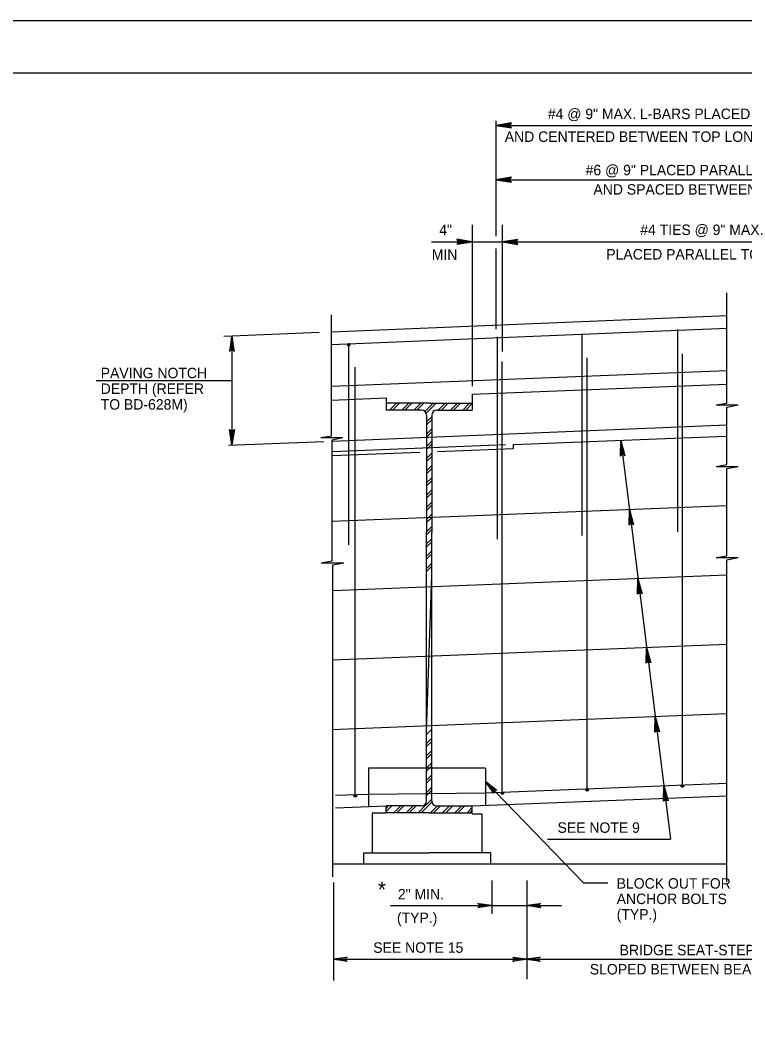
# Model space of a CAD drawing. Extents: x 640009 to 641706, y 298547 to 299735.
# Drawn here: x 641275 to 641482.9, y 299442.5 to 299735.2 of the extents above; entities that cross this region are included whole.
import ezdxf

# ---------------------------------------------------------------- set-up
doc = ezdxf.new("R2010")
doc.units = 0
doc.layers.add('1', color=7, linetype='Continuous')
doc.layers.add('PLT-BNDY', color=7, linetype='Continuous')

msp = doc.modelspace()

# ---------------------------------------------------------------- linework, layer by layer
at = {"layer": '1'}
for p, q in [((640890.47, 299720.17), (641676.47, 299720.17)), ((640890.47, 299720.17), (641676.47, 299720.17)), ((641411.49, 299706.36), (641411.49, 299673.27)), ((641411.49, 299705.06), (641557.24, 299705.06)), ((641411.49, 299689.46), (641557.24, 299689.46)), ((641404.74, 299676.52), (641404.74, 299630.22)), ((641413.37, 299676.52), (641413.37, 299640.22)), ((641393.08, 299671.65), (641571.62, 299671.65)), ((641411.49, 299669.78), (641411.49, 299646.6)), ((641477.87, 299625.37), (641477.87, 299657)), ((641364.37, 299615.97), (641364.37, 299650.72)), ((641364.37, 299645.85), (641477.87, 299650.47)), ((641364.37, 299642.22), (641477.87, 299646.84)), ((641463.62, 299646.47), (641463.62, 299588.47)), ((641333.47, 299644.59), (641360.82, 299645.7)), ((641335.78, 299613.33), (641335.78, 299644.68)), ((641411.87, 299644.35), (641411.87, 299586.35)), ((641436.24, 299645.22), (641436.24, 299587.35)), ((641369.24, 299642.6), (641369.24, 299584.72)), ((641413.37, 299513.42), (641413.37, 299637.35)), ((641437.74, 299514.43), (641437.74, 299638.35)), ((641465.12, 299515.28), (641465.12, 299639.47)), ((641364.37, 299630.22), (641477.87, 299634.72)), ((641371.12, 299512.67), (641371.12, 299635.72)), ((641296.78, 299631.9), (641335.78, 299631.9)), ((641404.74, 299627.9), (641477.87, 299630.84)), ((641364.37, 299626.22), (641379.99, 299626.93)), ((641379.99, 299626.93), (641379.99, 299623.35)), ((641392.37, 299625.35), (641379.99, 299625.35)), ((641392.37, 299625.35), (641379.99, 299625.35)), ((641379.99, 299625.35), (641379.99, 299623.35)), ((641392.37, 299625.35), (641379.99, 299625.35)), ((641379.99, 299625.35), (641379.99, 299624.35)), ((641392.37, 299625.35), (641379.99, 299625.35)), ((641379.99, 299625.35), (641379.99, 299623.35)), ((641392.37, 299625.35), (641404.74, 299625.35)), ((641392.37, 299625.35), (641404.74, 299625.35)), ((641392.37, 299625.35), (641404.74, 299625.35)), ((641392.37, 299625.35), (641404.74, 299625.35)), ((641404.74, 299627.9), (641404.74, 299623.35)), ((641404.74, 299625.35), (641404.74, 299623.35)), ((641404.74, 299625.35), (641404.74, 299624.35)), ((641404.74, 299625.35), (641404.74, 299623.35)), ((641474.74, 299624.87), (641477.87, 299625.37)), ((641390.12, 299623.35), (641379.99, 299623.35)), ((641390.12, 299623.35), (641379.99, 299623.35)), ((641390.12, 299623.35), (641379.99, 299623.35)), ((641394.62, 299623.35), (641404.74, 299623.35)), ((641394.62, 299623.35), (641404.74, 299623.35)), ((641394.62, 299623.35), (641404.74, 299623.35)), ((641474.74, 299624.87), (641481.12, 299624.87)), ((641477.87, 299624.22), (641481.12, 299624.87)), ((641477.87, 299615.9), (641477.87, 299624.22)), ((641477.99, 299624.87), (641477.99, 299624.87)), ((641391.62, 299621.85), (641391.62, 299588.22)), ((641391.62, 299621.85), (641391.62, 299588.22)), ((641391.62, 299621.85), (641391.62, 299588.22)), ((641393.12, 299621.85), (641393.12, 299588.22)), ((641393.12, 299621.85), (641393.12, 299588.22)), ((641393.12, 299621.85), (641393.12, 299588.22)), ((641364.49, 299614.5), (641477.87, 299619.12)), ((641334.74, 299613.29), (641362.1, 299614.4)), ((641361.24, 299615.47), (641364.37, 299615.97)), ((641361.24, 299615.47), (641367.62, 299615.47)), ((641364.49, 299614.85), (641367.62, 299615.47)), ((641364.49, 299615.47), (641364.49, 299615.47)), ((641364.49, 299580.1), (641364.49, 299614.85)), ((641416.62, 299613.47), (641465.12, 299615.39)), ((641447.35, 299614.69), (641461.7, 299500.28)), ((641465.12, 299615.39), (641477.87, 299615.9)), ((641477.87, 299607.73), (641477.87, 299615.9)), ((641364.49, 299611.47), (641414.24, 299613.47)), ((641364.49, 299610.35), (641389.74, 299611.35)), ((641394.74, 299611.47), (641416.62, 299612.35)), ((641416.62, 299612.35), (641416.62, 299613.47)), ((641474.74, 299607.23), (641477.87, 299607.73)), ((641474.74, 299607.23), (641481.12, 299607.23)), ((641477.87, 299606.58), (641481.12, 299607.23)), ((641477.87, 299581.6), (641477.87, 299606.58)), ((641477.99, 299607.23), (641477.99, 299607.23)), ((641364.49, 299591.5), (641477.87, 299595.99)), ((641391.62, 299511.33), (641391.62, 299588.22)), ((641391.62, 299511.33), (641391.62, 299588.22)), ((641391.62, 299511.33), (641391.62, 299588.22)), ((641393.12, 299511.33), (641393.12, 299588.22)), ((641393.12, 299511.33), (641393.12, 299588.22)), ((641393.12, 299511.33), (641393.12, 299588.22)), ((641474.74, 299581.1), (641477.87, 299581.6)), ((641361.37, 299579.6), (641364.49, 299580.1)), ((641361.37, 299579.6), (641367.87, 299579.6)), ((641364.62, 299579.6), (641364.62, 299579.6)), ((641364.74, 299578.97), (641367.87, 299579.6)), ((641364.74, 299489.46), (641364.74, 299578.97)), ((641474.74, 299581.1), (641481.12, 299581.1)), ((641477.87, 299580.45), (641481.12, 299581.1)), ((641477.87, 299488.08), (641477.87, 299580.45)), ((641477.99, 299581.1), (641477.99, 299581.1)), ((641364.74, 299571.6), (641477.87, 299576.09)), ((641364.74, 299551.7), (641477.87, 299556.18)), ((641364.46, 299531.77), (641477.87, 299536.29)), ((641374.92, 299520.65), (641374.92, 299509.6)), ((641408.56, 299520.65), (641374.92, 299520.65)), ((641408.56, 299520.65), (641408.56, 299509.98)), ((641408.56, 299516.78), (641436.71, 299487.74)), ((641408.56, 299513.6), (641477.87, 299516.36)), ((641365.49, 299512.85), (641374.92, 299513.22)), ((641374.92, 299513.22), (641408.56, 299513.6)), ((641404.74, 299509.83), (641477.87, 299512.74)), ((641365.49, 299509.23), (641379.99, 299509.8)), ((641390.12, 299509.83), (641379.99, 299509.83)), ((641379.99, 299507.83), (641379.99, 299509.83)), ((641390.12, 299509.83), (641379.99, 299509.83)), ((641379.99, 299507.83), (641379.99, 299509.83)), ((641390.12, 299509.83), (641379.99, 299509.83)), ((641379.99, 299507.83), (641379.99, 299509.83)), ((641394.62, 299509.83), (641404.74, 299509.83)), ((641394.62, 299509.83), (641404.74, 299509.83)), ((641394.62, 299509.83), (641404.74, 299509.83)), ((641404.74, 299507.83), (641404.74, 299509.83)), ((641404.74, 299507.83), (641404.74, 299509.83)), ((641404.74, 299507.83), (641404.74, 299509.83)), ((641375.99, 299507.83), (641379.99, 299507.83)), ((641375.99, 299507.58), (641375.99, 299496.33)), ((641392.37, 299507.83), (641379.99, 299507.83)), ((641392.37, 299507.83), (641379.99, 299507.83)), ((641392.37, 299507.83), (641379.99, 299507.83)), ((641392.37, 299507.83), (641404.74, 299507.83)), ((641392.37, 299507.83), (641404.74, 299507.83)), ((641392.37, 299507.83), (641404.74, 299507.83)), ((641404.74, 299507.58), (641407.49, 299507.58)), ((641407.49, 299507.58), (641407.49, 299496.33)), ((641426.31, 299500.28), (641461.7, 299500.28)), ((641373.49, 299496.33), (641373.49, 299493.21)), ((641373.49, 299496.33), (641392.37, 299496.33)), ((641409.99, 299496.33), (641392.37, 299496.33)), ((641409.99, 299496.33), (641409.99, 299493.21)), ((641364.74, 299493.21), (641477.87, 299493.21)), ((641364.87, 299487.83), (641364.87, 299459.71)), ((641410.37, 299488.46), (641410.37, 299478.83)), ((641420.37, 299488.46), (641420.37, 299460.08)), ((641436.71, 299487.74), (641443.62, 299487.74)), ((641381.3, 299481.21), (641410.37, 299481.21)), ((641410.37, 299481.21), (641420.37, 299481.21)), ((641420.37, 299481.21), (641430.37, 299481.21)), ((641364.87, 299465.83), (641420.24, 299465.83)), ((641420.24, 299465.83), (641541.87, 299465.83))]:
    msp.add_line(p, q, dxfattribs=at)
for points in [[(641415.78, 299705.58), (641415.6, 299705.27), (641411.54, 299705.04), (641415.78, 299705.58), (641415.99, 299705.77), (641411.54, 299705.04), (641415.6, 299704.85), (641415.76, 299704.54), (641411.54, 299705.04), (641415.99, 299704.32), (641415.76, 299704.54)], [(641415.78, 299689.98), (641415.6, 299689.66), (641411.54, 299689.44), (641415.78, 299689.98), (641415.99, 299690.17), (641411.54, 299689.44), (641415.6, 299689.24), (641415.76, 299688.94), (641411.54, 299689.44), (641415.99, 299688.72), (641415.76, 299688.94)], [(641400.5, 299671.12), (641400.67, 299671.43), (641404.74, 299671.65), (641400.5, 299671.12), (641400.29, 299670.93), (641404.74, 299671.65), (641400.67, 299671.85), (641400.51, 299672.16), (641404.74, 299671.65), (641400.29, 299672.38), (641400.51, 299672.16)], [(641417.65, 299672.18), (641417.48, 299671.86), (641413.41, 299671.64), (641417.65, 299672.18), (641417.87, 299672.36), (641413.41, 299671.64), (641417.48, 299671.44), (641417.64, 299671.14), (641413.41, 299671.64), (641417.87, 299670.91), (641417.64, 299671.14)], [(641336.3, 299640.39), (641335.99, 299640.57), (641335.76, 299644.64), (641336.3, 299640.39), (641336.49, 299640.18), (641335.76, 299644.64), (641335.57, 299640.57), (641335.26, 299640.41), (641335.76, 299644.64), (641335.04, 299640.18), (641335.26, 299640.41)], [(641369.24, 299642.1), (641369.24, 299642.1), (641369.24, 299642.22), (641369.37, 299642.22), (641369.37, 299642.22), (641369.37, 299642.1), (641369.37, 299642.1), (641369.37, 299641.97), (641369.24, 299641.97), (641369.24, 299641.97), (641369.12, 299642.1), (641369.12, 299642.22), (641369.12, 299642.22), (641369.24, 299642.22), (641369.24, 299642.35), (641369.37, 299642.35), (641369.49, 299642.22), (641369.49, 299642.1), (641369.49, 299641.97), (641369.37, 299641.85), (641369.37, 299641.85), (641369.24, 299641.85), (641369.12, 299641.97), (641368.99, 299642.1), (641368.99, 299642.22), (641369.12, 299642.22), (641369.12, 299642.35), (641369.24, 299642.35), (641369.37, 299642.35), (641369.49, 299642.35), (641369.62, 299642.22), (641369.62, 299642.22), (641369.62, 299642.1), (641369.62, 299641.97), (641369.49, 299641.97), (641369.49, 299641.85), (641369.37, 299641.85), (641369.24, 299641.85), (641369.24, 299641.85), (641369.12, 299641.85), (641368.99, 299641.85), (641368.99, 299641.97), (641368.99, 299642.1), (641368.99, 299642.1), (641368.99, 299642.22), (641368.99, 299642.35), (641369.12, 299642.35), (641369.24, 299642.35), (641369.37, 299642.47), (641369.37, 299642.35), (641369.49, 299642.35), (641369.24, 299642.1)], [(641379.99, 299624.97), (641380.37, 299625.35)], [(641380.99, 299623.35), (641382.99, 299625.35)], [(641381.87, 299623.35), (641383.87, 299625.35)], [(641384.49, 299623.35), (641386.49, 299625.35)], [(641385.37, 299623.35), (641387.37, 299625.35)], [(641387.99, 299623.35), (641389.99, 299625.35)], [(641388.87, 299623.35), (641390.87, 299625.35)], [(641391.12, 299622.97), (641393.49, 299625.35)], [(641391.49, 299622.47), (641394.37, 299625.35)], [(641394.99, 299623.35), (641396.99, 299625.35)], [(641395.87, 299623.35), (641397.87, 299625.35)], [(641398.49, 299623.35), (641400.49, 299625.35)], [(641399.37, 299623.35), (641401.37, 299625.35)], [(641401.99, 299623.35), (641403.99, 299625.35)], [(641402.87, 299623.35), (641404.74, 299625.22)], [(641404.62, 299623.35), (641404.74, 299623.47)], [(641391.62, 299619.97), (641393.12, 299621.47)], [(641391.62, 299619.1), (641393.12, 299620.6)], [(641336.3, 299617.62), (641335.99, 299617.44), (641335.76, 299613.38), (641336.3, 299617.62), (641336.49, 299617.83), (641335.76, 299613.38), (641335.57, 299617.44), (641335.26, 299617.6), (641335.76, 299613.38), (641335.04, 299617.83), (641335.26, 299617.6)], [(641391.62, 299616.47), (641393.12, 299617.97)], [(641391.62, 299615.6), (641393.12, 299617.1)], [(641391.62, 299612.97), (641393.12, 299614.47)], [(641391.62, 299612.1), (641393.12, 299613.6)], [(641447.45, 299610.36), (641447.65, 299610.54), (641447.35, 299614.69), (641447.45, 299610.36), (641447.26, 299610.19), (641447.35, 299614.69), (641448.04, 299610.7), (641448.4, 299610.49), (641447.35, 299614.69), (641448.58, 299610.29), (641448.4, 299610.49)], [(641391.62, 299609.47), (641393.12, 299610.97)], [(641391.62, 299608.6), (641393.12, 299610.1)], [(641391.62, 299605.97), (641393.12, 299607.47)], [(641391.62, 299605.1), (641393.12, 299606.6)], [(641391.62, 299602.47), (641393.12, 299603.97)], [(641391.62, 299601.6), (641393.12, 299603.1)], [(641391.62, 299598.97), (641393.12, 299600.47)], [(641391.62, 299598.1), (641393.12, 299599.6)], [(641391.62, 299595.47), (641393.12, 299596.97)], [(641391.62, 299594.6), (641393.12, 299596.1)], [(641391.62, 299591.97), (641393.12, 299593.47)], [(641449.94, 299590.55), (641450.14, 299590.73), (641449.84, 299594.88), (641449.94, 299590.55), (641449.74, 299590.38), (641449.84, 299594.88), (641450.52, 299590.89), (641450.89, 299590.68), (641449.84, 299594.88), (641451.06, 299590.48), (641450.89, 299590.68)], [(641391.62, 299591.1), (641393.12, 299592.6)], [(641391.62, 299588.47), (641393.12, 299589.97)], [(641391.62, 299587.6), (641393.12, 299589.1)], [(641391.62, 299584.97), (641393.12, 299586.47)], [(641391.62, 299584.1), (641393.12, 299585.6)], [(641391.62, 299581.47), (641393.12, 299582.97)], [(641391.62, 299580.6), (641393.12, 299582.1)], [(641391.62, 299577.97), (641393.12, 299579.47)], [(641391.62, 299577.1), (641393.12, 299578.6)], [(641391.62, 299531.21), (641393.12, 299575.97)], [(641452.42, 299570.75), (641452.62, 299570.92), (641452.32, 299575.07), (641452.42, 299570.75), (641452.22, 299570.57), (641452.32, 299575.07), (641453.01, 299571.09), (641453.37, 299570.87), (641452.32, 299575.07), (641453.54, 299570.68), (641453.37, 299570.87)], [(641454.91, 299550.94), (641455.1, 299551.12), (641454.8, 299555.27), (641454.91, 299550.94), (641454.71, 299550.76), (641454.8, 299555.27), (641455.49, 299551.28), (641455.85, 299551.07), (641454.8, 299555.27), (641456.03, 299550.87), (641455.85, 299551.07)], [(641457.39, 299531.14), (641457.59, 299531.32), (641457.29, 299535.47), (641457.39, 299531.14), (641457.19, 299530.97), (641457.29, 299535.47), (641457.97, 299531.48), (641458.34, 299531.27), (641457.29, 299535.47), (641458.51, 299531.07), (641458.34, 299531.27)], [(641391.62, 299530.33), (641393.12, 299531.83)], [(641391.62, 299527.71), (641393.12, 299529.21)], [(641391.62, 299526.83), (641393.12, 299528.33)], [(641391.62, 299524.21), (641393.12, 299525.71)], [(641391.62, 299523.33), (641393.12, 299524.83)], [(641391.62, 299520.71), (641393.12, 299522.21)], [(641391.62, 299519.83), (641393.12, 299521.33)], [(641391.62, 299517.21), (641393.12, 299518.71)], [(641391.62, 299516.33), (641393.12, 299517.83)], [(641391.62, 299513.71), (641393.12, 299515.21)], [(641391.62, 299512.83), (641393.12, 299514.33)], [(641410.91, 299513.84), (641411.01, 299514.1), (641408.56, 299516.78), (641410.91, 299513.84), (641410.91, 299513.49), (641408.56, 299516.78), (641411.27, 299514.37), (641411.54, 299514.45), (641408.56, 299516.78), (641411.8, 299514.36), (641411.54, 299514.45)], [(641437.74, 299514.43), (641437.74, 299514.43), (641437.74, 299514.55), (641437.74, 299514.55), (641437.87, 299514.55), (641437.87, 299514.43), (641437.87, 299514.3), (641437.87, 299514.3), (641437.74, 299514.3), (641437.62, 299514.3), (641437.62, 299514.43), (641437.62, 299514.43), (641437.62, 299514.55), (641437.74, 299514.55), (641437.74, 299514.55), (641437.87, 299514.55), (641437.99, 299514.55), (641437.99, 299514.43), (641437.99, 299514.3), (641437.87, 299514.18), (641437.74, 299514.18), (641437.62, 299514.18), (641437.49, 299514.3), (641437.49, 299514.43), (641437.49, 299514.55), (641437.49, 299514.55), (641437.62, 299514.68), (641437.74, 299514.68), (641437.87, 299514.68), (641437.99, 299514.68), (641437.99, 299514.55), (641437.99, 299514.55), (641437.99, 299514.43), (641437.99, 299514.3), (641437.99, 299514.18), (641437.99, 299514.18), (641437.87, 299514.18), (641437.74, 299514.05), (641437.62, 299514.18), (641437.62, 299514.18), (641437.49, 299514.18), (641437.49, 299514.3), (641437.37, 299514.43), (641437.37, 299514.43), (641437.49, 299514.55), (641437.49, 299514.68), (641437.49, 299514.68), (641437.62, 299514.68), (641437.74, 299514.68), (641437.87, 299514.68), (641437.99, 299514.68), (641437.74, 299514.43)], [(641459.88, 299511.31), (641460.07, 299511.49), (641459.77, 299515.64), (641459.88, 299511.31), (641459.68, 299511.13), (641459.77, 299515.64), (641460.46, 299511.65), (641460.82, 299511.44), (641459.77, 299515.64), (641461, 299511.24), (641460.82, 299511.44)], [(641465.12, 299515.41), (641465.12, 299515.53), (641465.12, 299515.53), (641465.12, 299515.53), (641465.24, 299515.53), (641465.24, 299515.41), (641465.24, 299515.41), (641465.12, 299515.28), (641465.12, 299515.28), (641464.99, 299515.28), (641464.99, 299515.41), (641464.99, 299515.53), (641464.99, 299515.53), (641464.99, 299515.66), (641465.12, 299515.66), (641465.24, 299515.66), (641465.24, 299515.53), (641465.37, 299515.41), (641465.37, 299515.28), (641465.24, 299515.28), (641465.12, 299515.16), (641464.99, 299515.16), (641464.87, 299515.28), (641464.87, 299515.41), (641464.87, 299515.53), (641464.87, 299515.66), (641464.99, 299515.66), (641465.12, 299515.66), (641465.24, 299515.66), (641465.37, 299515.66), (641465.37, 299515.66), (641465.37, 299515.53), (641465.37, 299515.41), (641465.37, 299515.28), (641465.37, 299515.28), (641465.24, 299515.16), (641465.24, 299515.16), (641465.12, 299515.16), (641464.99, 299515.16), (641464.87, 299515.16), (641464.87, 299515.28), (641464.74, 299515.28), (641464.74, 299515.41), (641464.74, 299515.53), (641464.74, 299515.53), (641464.87, 299515.66), (641464.87, 299515.66), (641464.99, 299515.78), (641465.12, 299515.78), (641465.24, 299515.78), (641465.24, 299515.66), (641465.12, 299515.41)], [(641371.12, 299512.67), (641371.12, 299512.79), (641371.12, 299512.79), (641371.24, 299512.79), (641371.24, 299512.79), (641371.37, 299512.79), (641371.24, 299512.67), (641371.24, 299512.54), (641371.12, 299512.54), (641371.12, 299512.54), (641370.99, 299512.67), (641370.99, 299512.79), (641371.12, 299512.79), (641371.12, 299512.92), (641371.24, 299512.92), (641371.24, 299512.92), (641371.37, 299512.79), (641371.37, 299512.67), (641371.37, 299512.54), (641371.37, 299512.54), (641371.24, 299512.42), (641371.12, 299512.54), (641370.99, 299512.54), (641370.87, 299512.67), (641370.87, 299512.79), (641370.99, 299512.92), (641371.12, 299512.92), (641371.12, 299513.04), (641371.24, 299513.04), (641371.37, 299512.92), (641371.49, 299512.92), (641371.49, 299512.79), (641371.49, 299512.67), (641371.49, 299512.54), (641371.49, 299512.54), (641371.37, 299512.42), (641371.24, 299512.42), (641371.24, 299512.42), (641371.12, 299512.42), (641370.99, 299512.42), (641370.87, 299512.54), (641370.87, 299512.54), (641370.87, 299512.67), (641370.87, 299512.79), (641370.87, 299512.79), (641370.87, 299512.92), (641370.99, 299512.92), (641371.12, 299513.04), (641371.24, 299513.04), (641371.24, 299513.04), (641371.37, 299512.92), (641371.12, 299512.67)], [(641391.49, 299510.08), (641393.12, 299511.71)], [(641413.37, 299513.42), (641413.37, 299513.55), (641413.37, 299513.55), (641413.49, 299513.55), (641413.49, 299513.55), (641413.49, 299513.42), (641413.49, 299513.42), (641413.49, 299513.3), (641413.37, 299513.3), (641413.24, 299513.3), (641413.24, 299513.42), (641413.24, 299513.55), (641413.24, 299513.55), (641413.37, 299513.55), (641413.37, 299513.67), (641413.49, 299513.67), (641413.62, 299513.55), (641413.62, 299513.42), (641413.62, 299513.3), (641413.49, 299513.17), (641413.37, 299513.17), (641413.24, 299513.17), (641413.24, 299513.3), (641413.12, 299513.42), (641413.12, 299513.55), (641413.24, 299513.67), (641413.24, 299513.67), (641413.37, 299513.67), (641413.49, 299513.67), (641413.62, 299513.67), (641413.62, 299513.55), (641413.74, 299513.55), (641413.74, 299513.42), (641413.74, 299513.3), (641413.62, 299513.3), (641413.62, 299513.17), (641413.49, 299513.17), (641413.37, 299513.17), (641413.24, 299513.17), (641413.24, 299513.17), (641413.12, 299513.3), (641413.12, 299513.3), (641413.12, 299513.42), (641413.12, 299513.55), (641413.12, 299513.55), (641413.12, 299513.67), (641413.24, 299513.67), (641413.37, 299513.8), (641413.37, 299513.8), (641413.49, 299513.67), (641413.62, 299513.67), (641413.37, 299513.42)], [(641379.99, 299508.21), (641381.62, 299509.83)], [(641379.99, 299509.08), (641380.74, 299509.83)], [(641382.24, 299507.83), (641384.24, 299509.83)], [(641383.12, 299507.83), (641385.12, 299509.83)], [(641385.74, 299507.83), (641387.74, 299509.83)], [(641386.62, 299507.83), (641388.62, 299509.83)], [(641389.24, 299507.83), (641391.37, 299510.08)], [(641390.12, 299507.83), (641393.24, 299510.96)], [(641392.74, 299507.83), (641394.74, 299509.83)], [(641393.62, 299507.83), (641395.62, 299509.83)], [(641396.24, 299507.83), (641398.24, 299509.83)], [(641397.12, 299507.83), (641399.12, 299509.83)], [(641399.74, 299507.83), (641401.74, 299509.83)], [(641400.62, 299507.83), (641402.62, 299509.83)], [(641403.24, 299507.83), (641404.74, 299509.33)], [(641404.12, 299507.83), (641404.74, 299508.46)], [(641406.62, 299481.71), (641406.74, 299481.46), (641410.37, 299481.21), (641406.62, 299481.71), (641406.37, 299481.83), (641410.37, 299481.21), (641406.74, 299481.08), (641406.62, 299480.83), (641410.37, 299481.21), (641406.37, 299480.58), (641406.62, 299480.83)], [(641424.12, 299480.83), (641423.99, 299481.08), (641420.37, 299481.21), (641424.12, 299480.83), (641424.37, 299480.58), (641420.37, 299481.21), (641423.99, 299481.46), (641424.12, 299481.71), (641420.37, 299481.21), (641424.37, 299481.83), (641424.12, 299481.71)], [(641368.62, 299465.33), (641368.49, 299465.58), (641364.87, 299465.83), (641368.62, 299465.33), (641368.87, 299465.21), (641364.87, 299465.83), (641368.49, 299465.96), (641368.62, 299466.33), (641364.87, 299465.83), (641368.87, 299466.46), (641368.62, 299466.33)], [(641416.49, 299466.33), (641416.62, 299466.08), (641420.24, 299465.83), (641416.49, 299466.33), (641416.37, 299466.46), (641420.24, 299465.83), (641416.62, 299465.71), (641416.49, 299465.33), (641420.24, 299465.83), (641416.37, 299465.21), (641416.49, 299465.33)], [(641423.99, 299465.33), (641423.87, 299465.58), (641420.24, 299465.83), (641423.99, 299465.33), (641424.24, 299465.21), (641420.24, 299465.83), (641423.87, 299465.96), (641423.99, 299466.33), (641420.24, 299465.83), (641424.24, 299466.46), (641423.99, 299466.33)]]:
    msp.add_lwpolyline(points, dxfattribs=at)
for centre, start, end in [((641390.16, 299621.87), 0, 90), ((641390.16, 299621.87), 0, 90), ((641390.16, 299621.87), 0, 90), ((641394.62, 299621.87), 90, 180), ((641394.62, 299621.87), 90, 180), ((641394.62, 299621.87), 90, 180), ((641390.16, 299511.29), 270, 0), ((641390.16, 299511.29), 270, 0), ((641390.16, 299511.29), 270, 0), ((641394.62, 299511.29), 180, 270), ((641394.62, 299511.29), 180, 270), ((641394.62, 299511.29), 180, 270)]:
    msp.add_arc(centre, 1.49, start, end, dxfattribs=at)
at = {"layer": 'PLT-BNDY'}
msp.add_lwpolyline([(640850.47, 299735.17), (641691.47, 299735.17), (641691.47, 299141.17), (640850.47, 299141.17)], close=True, dxfattribs=at)

# ---------------------------------------------------------------- texts
at = {"layer": '1'}
for s, height, p in [('#4 @ 9" MAX. L-BARS PLACED PARALLEL TO', 3, (641426.44, 299706.86)), ('AND CENTERED BETWEEN TOP LONGITUDINAL SLAB BARS', 3, (641414.08, 299700.32)), ('#6 @ 9" PLACED PARALLEL TO BEAMS', 3, (641437.29, 299690.73)), ('AND SPACED BETWEEN BEAM FLANGES', 3, (641439.53, 299685.19)), ('4"', 3, (641395.26, 299673.54)), ('#4 TIES @ 9" MAX.', 3, (641452.97, 299673.61)), ('MIN', 3, (641393.13, 299666.46)), ('PLACED PARALLEL TO BEAMS', 3, (641443.23, 299666.57)), ('PAVING NOTCH', 3, (641298.08, 299632.51)), ('DEPTH (REFER', 3, (641298.08, 299628.01)), ('TO BD-628M)', 3, (641298.08, 299623.51)), ('SEE NOTE 9', 3, (641429.22, 299502.1)), ('*', 4.46, (641377.65, 299483.64)), ('BLOCK OUT FOR', 3, (641446.2, 299486.08)), ('2" MIN.', 3, (641383.4, 299482.98)), ('ANCHOR BOLTS', 3, (641446.2, 299481.65)), (' (TYP.)', 3, (641382.01, 299476.21)), ('(TYP.)', 3, (641446.2, 299477.22)), ('SEE NOTE 15', 3, (641376.32, 299467.67)), ('BRIDGE SEAT-STEPPED OR', 3, (641447.06, 299466.96)), ('SLOPED BETWEEN BEARING AREAS', 3, (641438.49, 299461.46))]:
    msp.add_text(s, height=height, dxfattribs=at).set_placement(p)

doc.saveas('drawing.dxf')
